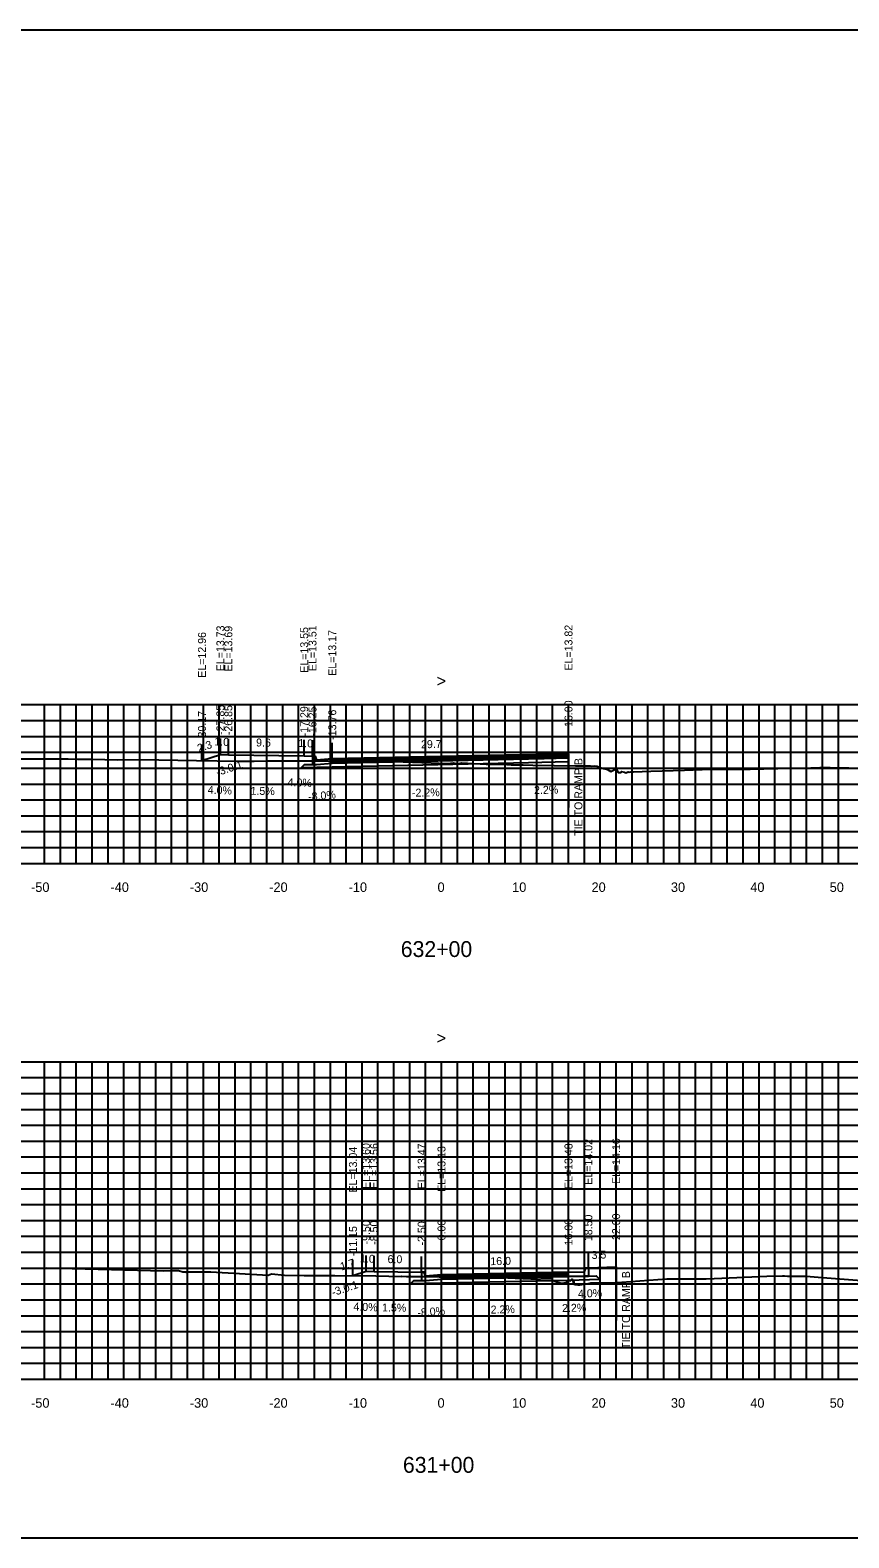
# Model space of a CAD drawing. Extents: x 1797645 to 1803805, y 248417 to 250269.
# Drawn here: x 1803599.2 to 1803702.3, y 250079.4 to 250269.4 of the extents above; entities that cross this region are included whole.
import ezdxf

# ---------------------------------------------------------------- set-up
doc = ezdxf.new("R2010")
doc.units = 0
for name, color, linetype in [('1', 7, 'Continuous'), ('10', 7, 'Continuous'), ('3', 7, 'Continuous'), ('4', 7, 'Continuous'), ('60', 7, 'Continuous'), ('BASE', 7, 'Continuous'), ('CL-CNST', 7, 'Continuous'), ('Level 62', 7, 'Continuous'), ('LOWER BINDER', 7, 'Continuous'), ('M-ROADS', 7, 'Continuous'), ('UPPER BINDER', 7, 'Continuous'), ('WEARING', 7, 'Continuous')]:
    doc.layers.add(name, color=color, linetype=linetype)

msp = doc.modelspace()

# ---------------------------------------------------------------- linework, layer by layer
for p, q in [((1803620.83, 250177.39), (1803620.83, 250179.39)), ((1803623.15, 250178.16), (1803623.15, 250180.16)), ((1803624.15, 250178.12), (1803624.15, 250180.12)), ((1803633.71, 250177.98), (1803633.71, 250179.98)), ((1803634.75, 250177.94), (1803634.75, 250179.94)), ((1803637.24, 250177.6), (1803637.24, 250179.6)), ((1803667, 250178.25), (1803667, 250180.25)), ((1803639.85, 250112.48), (1803639.85, 250114.48)), ((1803641.5, 250113.03), (1803641.5, 250115.03)), ((1803642.5, 250112.99), (1803642.5, 250114.99)), ((1803648.5, 250112.9), (1803648.5, 250114.9)), ((1803648.5, 250112.9), (1803648.5, 250114.9)), ((1803651, 250112.56), (1803651, 250114.56)), ((1803667, 250112.91), (1803667, 250114.91)), ((1803669.5, 250113.45), (1803669.5, 250115.45)), ((1803673, 250113.59), (1803673, 250115.59))]:
    msp.add_line(p, q)
for points in [[(1803501, 250079.43), (1803801, 250079.43), (1803801, 250269.43), (1803501, 250269.43)], [(1803637.24, 250177.6), (1803635.24, 250177.44), (1803635.08, 250177.94), (1803634.75, 250177.94), (1803634.74, 250176.91), (1803635.24, 250176.91), (1803637.24, 250177.07)], [(1803651, 250112.56), (1803649, 250112.4), (1803648.83, 250112.9), (1803648.5, 250112.9), (1803648.5, 250111.87), (1803649, 250111.87), (1803651, 250112.03)], [(1803667, 250112.91), (1803669, 250112.95), (1803669.17, 250113.45), (1803669.5, 250113.45), (1803669.5, 250112.42), (1803669, 250112.42), (1803667, 250112.38)]]:
    msp.add_lwpolyline(points, close=True)
at = {"layer": '3'}
for p, q in [((1803667, 250178.25), (1803667, 250171.47)), ((1803673, 250113.59), (1803673, 250106.81))]:
    msp.add_line(p, q, dxfattribs=at)
at = {"layer": '60'}
for p, q in [((1803501, 250164.43), (1803801, 250164.43)), ((1803601, 250164.37), (1803601, 250164.43)), ((1803611, 250164.37), (1803611, 250164.43)), ((1803621, 250164.37), (1803621, 250164.43)), ((1803631, 250164.37), (1803631, 250164.43)), ((1803641, 250164.37), (1803641, 250164.43)), ((1803651, 250164.37), (1803651, 250164.43)), ((1803661, 250164.37), (1803661, 250164.43)), ((1803671, 250164.37), (1803671, 250164.43)), ((1803681, 250164.37), (1803681, 250164.43)), ((1803691, 250164.37), (1803691, 250164.43)), ((1803701, 250164.37), (1803701, 250164.43)), ((1803501, 250099.43), (1803801, 250099.43)), ((1803601, 250099.37), (1803601, 250099.43)), ((1803611, 250099.37), (1803611, 250099.43)), ((1803621, 250099.37), (1803621, 250099.43)), ((1803631, 250099.37), (1803631, 250099.43)), ((1803641, 250099.37), (1803641, 250099.43)), ((1803651, 250099.37), (1803651, 250099.43)), ((1803661, 250099.37), (1803661, 250099.43)), ((1803671, 250099.37), (1803671, 250099.43)), ((1803681, 250099.37), (1803681, 250099.43)), ((1803691, 250099.37), (1803691, 250099.43)), ((1803701, 250099.37), (1803701, 250099.43))]:
    msp.add_line(p, q, dxfattribs=at)
at = {"layer": 'BASE'}
for points in [[(1803637.24, 250177.07), (1803661.94, 250177.61), (1803663.94, 250177.66), (1803667, 250177.72), (1803667, 250177.22), (1803661.94, 250177.11), (1803637.24, 250176.57), (1803633.34, 250176.48), (1803633.74, 250176.89), (1803634.74, 250176.91), (1803635.24, 250176.91)], [(1803651, 250112.03), (1803667, 250112.38), (1803669, 250112.42), (1803669.5, 250112.42), (1803670.5, 250112.45), (1803670.98, 250111.97), (1803667, 250111.88), (1803651, 250111.53), (1803647.09, 250111.44), (1803647.5, 250111.85), (1803648.5, 250111.87), (1803649, 250111.87)]]:
    msp.add_lwpolyline(points, close=True, dxfattribs=at)
at = {"layer": 'CL-CNST'}
for points in [[(1803620.83, 250177.39), (1803623.15, 250178.16), (1803624.15, 250178.12), (1803633.71, 250177.98), (1803634.75, 250177.94), (1803635.08, 250177.94), (1803635.24, 250177.44), (1803637.24, 250177.6), (1803661.94, 250178.14), (1803667, 250178.25)], [(1803639.85, 250112.48), (1803641.5, 250113.03), (1803642.5, 250112.99), (1803648.5, 250112.9), (1803648.5, 250112.9), (1803648.83, 250112.9), (1803649, 250112.4), (1803651, 250112.56), (1803667, 250112.91), (1803669, 250112.95), (1803669.17, 250113.45), (1803669.5, 250113.45), (1803673, 250113.59)]]:
    msp.add_lwpolyline(points, dxfattribs=at)
at = {"layer": 'Level 62'}
for p, q in [((1803501, 250184.43), (1803801, 250184.43)), ((1803601, 250164.43), (1803601, 250184.43)), ((1803603, 250164.43), (1803603, 250184.43)), ((1803605, 250164.43), (1803605, 250184.43)), ((1803607, 250164.43), (1803607, 250184.43)), ((1803609, 250164.43), (1803609, 250184.43)), ((1803611, 250164.43), (1803611, 250184.43)), ((1803613, 250164.43), (1803613, 250184.43)), ((1803615, 250164.43), (1803615, 250184.43)), ((1803617, 250164.43), (1803617, 250184.43)), ((1803619, 250164.43), (1803619, 250184.43)), ((1803621, 250164.43), (1803621, 250184.43)), ((1803623, 250164.43), (1803623, 250184.43)), ((1803625, 250164.43), (1803625, 250184.43)), ((1803627, 250164.43), (1803627, 250184.43)), ((1803629, 250164.43), (1803629, 250184.43)), ((1803631, 250164.43), (1803631, 250184.43)), ((1803633, 250164.43), (1803633, 250184.43)), ((1803635, 250164.43), (1803635, 250184.43)), ((1803637, 250164.43), (1803637, 250184.43)), ((1803639, 250164.43), (1803639, 250184.43)), ((1803641, 250164.43), (1803641, 250184.43)), ((1803643, 250164.43), (1803643, 250184.43)), ((1803645, 250164.43), (1803645, 250184.43)), ((1803647, 250164.43), (1803647, 250184.43)), ((1803649, 250164.43), (1803649, 250184.43)), ((1803651, 250164.43), (1803651, 250184.43)), ((1803653, 250164.43), (1803653, 250184.43)), ((1803655, 250164.43), (1803655, 250184.43)), ((1803657, 250164.43), (1803657, 250184.43)), ((1803659, 250164.43), (1803659, 250184.43)), ((1803661, 250164.43), (1803661, 250184.43)), ((1803663, 250164.43), (1803663, 250184.43)), ((1803665, 250164.43), (1803665, 250184.43)), ((1803667, 250164.43), (1803667, 250184.43)), ((1803669, 250164.43), (1803669, 250184.43)), ((1803671, 250164.43), (1803671, 250184.43)), ((1803673, 250164.43), (1803673, 250184.43)), ((1803675, 250164.43), (1803675, 250184.43)), ((1803677, 250164.43), (1803677, 250184.43)), ((1803679, 250164.43), (1803679, 250184.43)), ((1803681, 250164.43), (1803681, 250184.43)), ((1803683, 250164.43), (1803683, 250184.43)), ((1803685, 250164.43), (1803685, 250184.43)), ((1803687, 250164.43), (1803687, 250184.43)), ((1803689, 250164.43), (1803689, 250184.43)), ((1803691, 250164.43), (1803691, 250184.43)), ((1803693, 250164.43), (1803693, 250184.43)), ((1803695, 250164.43), (1803695, 250184.43)), ((1803697, 250164.43), (1803697, 250184.43)), ((1803699, 250164.43), (1803699, 250184.43)), ((1803701, 250164.43), (1803701, 250184.43)), ((1803501, 250182.43), (1803801, 250182.43)), ((1803501, 250180.43), (1803801, 250180.43)), ((1803501, 250178.43), (1803801, 250178.43)), ((1803501, 250176.43), (1803801, 250176.43)), ((1803501, 250174.43), (1803801, 250174.43)), ((1803501, 250172.43), (1803801, 250172.43)), ((1803501, 250170.43), (1803801, 250170.43)), ((1803501, 250168.43), (1803801, 250168.43)), ((1803501, 250166.43), (1803801, 250166.43)), ((1803501, 250164.43), (1803801, 250164.43)), ((1803501, 250139.43), (1803801, 250139.43)), ((1803601, 250099.43), (1803601, 250139.43)), ((1803603, 250099.43), (1803603, 250139.43)), ((1803605, 250099.43), (1803605, 250139.43)), ((1803607, 250099.43), (1803607, 250139.43)), ((1803609, 250099.43), (1803609, 250139.43)), ((1803611, 250099.43), (1803611, 250139.43)), ((1803613, 250099.43), (1803613, 250139.43)), ((1803615, 250099.43), (1803615, 250139.43)), ((1803617, 250099.43), (1803617, 250139.43)), ((1803619, 250099.43), (1803619, 250139.43)), ((1803621, 250099.43), (1803621, 250139.43)), ((1803623, 250099.43), (1803623, 250139.43)), ((1803625, 250099.43), (1803625, 250139.43)), ((1803627, 250099.43), (1803627, 250139.43)), ((1803629, 250099.43), (1803629, 250139.43)), ((1803631, 250099.43), (1803631, 250139.43)), ((1803633, 250099.43), (1803633, 250139.43)), ((1803635, 250099.43), (1803635, 250139.43)), ((1803637, 250099.43), (1803637, 250139.43)), ((1803639, 250099.43), (1803639, 250139.43)), ((1803641, 250099.43), (1803641, 250139.43)), ((1803643, 250099.43), (1803643, 250139.43)), ((1803645, 250099.43), (1803645, 250139.43)), ((1803647, 250099.43), (1803647, 250139.43)), ((1803649, 250099.43), (1803649, 250139.43)), ((1803651, 250099.43), (1803651, 250139.43)), ((1803653, 250099.43), (1803653, 250139.43)), ((1803655, 250099.43), (1803655, 250139.43)), ((1803657, 250099.43), (1803657, 250139.43)), ((1803659, 250099.43), (1803659, 250139.43)), ((1803661, 250099.43), (1803661, 250139.43)), ((1803663, 250099.43), (1803663, 250139.43)), ((1803665, 250099.43), (1803665, 250139.43)), ((1803667, 250099.43), (1803667, 250139.43)), ((1803669, 250099.43), (1803669, 250139.43)), ((1803671, 250099.43), (1803671, 250139.43)), ((1803673, 250099.43), (1803673, 250139.43)), ((1803675, 250099.43), (1803675, 250139.43)), ((1803677, 250099.43), (1803677, 250139.43)), ((1803679, 250099.43), (1803679, 250139.43)), ((1803681, 250099.43), (1803681, 250139.43)), ((1803683, 250099.43), (1803683, 250139.43)), ((1803685, 250099.43), (1803685, 250139.43)), ((1803687, 250099.43), (1803687, 250139.43)), ((1803689, 250099.43), (1803689, 250139.43)), ((1803691, 250099.43), (1803691, 250139.43)), ((1803693, 250099.43), (1803693, 250139.43)), ((1803695, 250099.43), (1803695, 250139.43)), ((1803697, 250099.43), (1803697, 250139.43)), ((1803699, 250099.43), (1803699, 250139.43)), ((1803701, 250099.43), (1803701, 250139.43)), ((1803501, 250137.43), (1803801, 250137.43)), ((1803501, 250135.43), (1803801, 250135.43)), ((1803501, 250133.43), (1803801, 250133.43)), ((1803501, 250131.43), (1803801, 250131.43)), ((1803501, 250129.43), (1803801, 250129.43)), ((1803501, 250127.43), (1803801, 250127.43)), ((1803501, 250125.43), (1803801, 250125.43)), ((1803501, 250123.43), (1803801, 250123.43)), ((1803501, 250121.43), (1803801, 250121.43)), ((1803501, 250119.43), (1803801, 250119.43)), ((1803501, 250117.43), (1803801, 250117.43)), ((1803501, 250115.43), (1803801, 250115.43)), ((1803501, 250113.43), (1803801, 250113.43)), ((1803501, 250111.43), (1803801, 250111.43)), ((1803501, 250109.43), (1803801, 250109.43)), ((1803501, 250107.43), (1803801, 250107.43)), ((1803501, 250105.43), (1803801, 250105.43)), ((1803501, 250103.43), (1803801, 250103.43)), ((1803501, 250101.43), (1803801, 250101.43)), ((1803501, 250099.43), (1803801, 250099.43))]:
    msp.add_line(p, q, dxfattribs=at)
at = {"layer": 'LOWER BINDER'}
for points in [[(1803667, 250177.72), (1803667, 250177.91), (1803637.24, 250177.26), (1803637.24, 250177.07)], [(1803667, 250112.38), (1803667, 250112.38), (1803667, 250112.57), (1803651, 250112.22), (1803651, 250112.03)]]:
    msp.add_lwpolyline(points, close=True, dxfattribs=at)
at = {"layer": 'M-ROADS'}
for points in [[(1803597.76, 250177.62), (1803599.6, 250177.61), (1803603.96, 250177.59), (1803605.15, 250177.58), (1803606.98, 250177.57), (1803610.2, 250177.49), (1803613.05, 250177.53), (1803620.12, 250177.4), (1803622.76, 250177.37), (1803625.38, 250177.33), (1803626.46, 250177.33), (1803627.39, 250177.33), (1803628.88, 250177.37), (1803634.65, 250177.36), (1803640.07, 250177.31), (1803641.61, 250177.33), (1803642.89, 250177.35), (1803646.18, 250177.24), (1803649.71, 250177.11), (1803651.75, 250177.02), (1803652.53, 250177.09), (1803653.05, 250176.99), (1803653.5, 250177.09), (1803656.62, 250176.92), (1803658.79, 250176.93), (1803659.25, 250176.9), (1803659.78, 250176.86), (1803660.67, 250176.85), (1803660.76, 250176.86), (1803661.28, 250176.85), (1803662.52, 250176.82), (1803667.9, 250176.73), (1803669.72, 250176.71), (1803669.91, 250176.68), (1803670.33, 250176.71), (1803670.59, 250176.68), (1803671.19, 250176.41), (1803671.9, 250176.26), (1803672.33, 250176.02), (1803672.84, 250176.26), (1803672.97, 250176.35), (1803672.99, 250176.38), (1803673.2, 250175.94), (1803673.26, 250175.89), (1803673.58, 250175.9), (1803673.59, 250175.9), (1803673.67, 250176), (1803674.05, 250175.91), (1803674.23, 250175.86), (1803674.5, 250175.97), (1803674.66, 250175.93), (1803674.86, 250175.97), (1803675.19, 250175.97), (1803677.35, 250176.03), (1803681.63, 250176.19), (1803684.94, 250176.31), (1803685.61, 250176.32), (1803687.27, 250176.32), (1803687.72, 250176.3), (1803687.76, 250176.3), (1803687.88, 250176.3), (1803689.9, 250176.3), (1803695.07, 250176.43), (1803697.54, 250176.48), (1803698.65, 250176.5), (1803699.9, 250176.5), (1803700.07, 250176.49), (1803702.33, 250176.49)], [(1803601.2, 250113.48), (1803615.97, 250113.08), (1803617.08, 250113.11), (1803617.87, 250113.12), (1803618.42, 250112.94), (1803618.83, 250112.94), (1803618.84, 250112.87), (1803619.05, 250112.94), (1803619.29, 250112.94), (1803621.95, 250112.96), (1803629.18, 250112.55), (1803629.59, 250112.69), (1803631.22, 250112.55), (1803633.7, 250112.5), (1803637.57, 250112.5), (1803642.73, 250112.44), (1803645.99, 250112.35), (1803646, 250112.38), (1803646.02, 250112.39), (1803646.58, 250112.35), (1803647.02, 250112.38), (1803647.09, 250112.39), (1803647.1, 250112.38), (1803647.81, 250112.38), (1803649.49, 250112.36), (1803650.69, 250112.34), (1803651.63, 250112.33), (1803651.99, 250112.33), (1803652.06, 250112.27), (1803652.28, 250112.32), (1803652.62, 250112.34), (1803652.65, 250112.34), (1803653.96, 250112.3), (1803656.52, 250112.31), (1803660.27, 250112.15), (1803663.21, 250112.03), (1803663.78, 250112.1), (1803664.82, 250112.1), (1803665.18, 250111.76), (1803666.11, 250111.53), (1803666.7, 250111.63), (1803667.13, 250111.87), (1803667.23, 250111.81), (1803667.23, 250111.85), (1803667.24, 250111.81), (1803667.25, 250111.87), (1803667.44, 250112.05), (1803667.55, 250111.81), (1803667.62, 250111.56), (1803667.63, 250111.69), (1803667.65, 250111.73), (1803667.71, 250111.4), (1803667.72, 250111.41), (1803667.72, 250111.41), (1803667.72, 250111.4), (1803667.73, 250111.4), (1803667.82, 250111.36), (1803667.88, 250111.35), (1803668.18, 250111.31), (1803668.44, 250111.32), (1803669.7, 250111.53), (1803669.82, 250111.55), (1803669.89, 250111.55), (1803670.25, 250111.56), (1803671.72, 250111.56), (1803672.59, 250111.56), (1803678.26, 250111.98), (1803679.4, 250112.06), (1803680.31, 250112.06), (1803681.82, 250112.06), (1803681.9, 250112.06), (1803683.15, 250112.06), (1803684.07, 250112.06), (1803684.36, 250112.06), (1803685.33, 250112.11), (1803691.98, 250112.41), (1803693.95, 250112.43), (1803694.2, 250112.43), (1803694.57, 250112.41), (1803696.49, 250112.41), (1803696.95, 250112.41), (1803698.45, 250112.3), (1803703.89, 250111.88)]]:
    msp.add_lwpolyline(points, dxfattribs=at)
at = {"layer": 'UPPER BINDER'}
for points in [[(1803667, 250177.91), (1803667, 250178.1), (1803637.24, 250177.45), (1803637.24, 250177.26)], [(1803667, 250112.57), (1803667, 250112.76), (1803651, 250112.41), (1803651, 250112.22)]]:
    msp.add_lwpolyline(points, close=True, dxfattribs=at)
at = {"layer": 'WEARING'}
for points in [[(1803667, 250178.1), (1803667, 250178.25), (1803637.24, 250177.6), (1803637.24, 250177.45)], [(1803667, 250112.76), (1803667, 250112.91), (1803651, 250112.56), (1803651, 250112.41)]]:
    msp.add_lwpolyline(points, close=True, dxfattribs=at)

# ---------------------------------------------------------------- texts
for p in [(1803622.78, 250175.41), (1803637.35, 250109.86)]:
    msp.add_text('-3.0:1', height=1, rotation=18.4349).set_placement(p)
at = {"layer": '1'}
for s, p in [('632+00', (1803645.87, 250152.63)), ('631+00', (1803646.14, 250087.63))]:
    msp.add_text(s, height=2, dxfattribs=at).set_placement(p)
at = {"layer": '10'}
for s, p in [('-50', (1803599.3, 250160.83)), ('-40', (1803609.3, 250160.83)), ('-30', (1803619.3, 250160.83)), ('-20', (1803629.3, 250160.83)), ('-10', (1803639.3, 250160.83)), ('0', (1803650.5, 250160.83)), ('10', (1803659.9, 250160.83)), ('20', (1803669.9, 250160.83)), ('30', (1803679.9, 250160.83)), ('40', (1803689.9, 250160.83)), ('50', (1803699.9, 250160.83)), ('-50', (1803599.3, 250095.83)), ('-40', (1803609.3, 250095.83)), ('-30', (1803619.3, 250095.83)), ('-20', (1803629.3, 250095.83)), ('-10', (1803639.3, 250095.83)), ('0', (1803650.5, 250095.83)), ('10', (1803659.9, 250095.83)), ('20', (1803669.9, 250095.83)), ('30', (1803679.9, 250095.83)), ('40', (1803689.9, 250095.83)), ('50', (1803699.9, 250095.83))]:
    msp.add_text(s, height=1.2, dxfattribs=at).set_placement(p)
at = {"layer": '3'}
for s, p in [('EL=13.73', (1803623.65, 250188.64)), ('EL=13.69', (1803624.65, 250188.6)), ('EL=13.55', (1803634.21, 250188.45)), ('EL=13.51', (1803635.25, 250188.66)), ('EL=13.82', (1803667.5, 250188.73)), ('EL=12.96', (1803621.33, 250187.82)), ('EL=13.17', (1803637.74, 250188.07)), ('16.00', (1803667.5, 250181.62)), ('-30.17', (1803621.33, 250179.85)), ('-27.85', (1803623.65, 250180.62)), ('-26.85', (1803624.65, 250180.58)), ('-17.29', (1803634.21, 250180.44)), ('-16.25', (1803635.25, 250180.4)), ('-13.76', (1803637.74, 250180.01)), ('TIE TO RAMP B', (1803668.75, 250167.9)), ('EL=14.02', (1803670, 250123.93)), ('EL=14.16', (1803673.5, 250124.02)), ('EL=13.04', (1803640.35, 250122.95)), ('EL=13.60', (1803642, 250123.42)), ('EL=13.56', (1803643, 250123.41)), ('EL=13.47', (1803649, 250123.37)), ('EL=13.47', (1803649, 250123.37)), ('EL=13.13', (1803651.5, 250123.03)), ('EL=13.48', (1803667.5, 250123.38)), ('18.50', (1803670, 250116.82)), ('22.00', (1803673.5, 250116.96)), ('-11.15', (1803640.35, 250114.93)), ('-9.50', (1803642, 250116.4)), ('-8.50', (1803643, 250116.36)), ('-2.50', (1803649, 250116.27)), ('-2.50', (1803649, 250116.27)), ('0.00', (1803651.5, 250116.92)), ('16.00', (1803667.5, 250116.28)), ('TIE TO RAMP B', (1803674.74, 250103.24))]:
    msp.add_text(s, height=1, rotation=90, dxfattribs=at).set_placement(p)
at = {"layer": '4'}
for s, rotation, p in [('2.3', 18.4349, (1803620.43, 250178.42)), ('1.0', 357.7094, (1803622.37, 250179.3)), ('9.6', 359.1406, (1803627.64, 250179.17)), ('1.0', 357.7094, (1803632.95, 250179.11)), ('29.7', 1.2603, (1803648.43, 250178.93)), ('4.0%', 357.7094, (1803631.6, 250174.18)), ('4.0%', 357.7094, (1803621.54, 250173.22)), ('1.5%', 359.1406, (1803626.94, 250173.08)), ('-8.0%', 4.5739, (1803634.24, 250172.34)), ('-2.2%', 1.2603, (1803647.29, 250172.82)), ('2.2%', 1.2603, (1803662.67, 250173.16)), ('1.7', 18.4349, (1803638.43, 250113.11)), ('1.0', 357.7094, (1803640.72, 250114.16)), ('6.0', 359.1406, (1803644.2, 250114.06)), ('16.0', 1.2603, (1803657.16, 250113.79)), ('3.5', 2.2906, (1803669.92, 250114.57)), ('4.0%', 2.2906, (1803668.21, 250109.69)), ('4.0%', 357.7094, (1803639.89, 250108.09)), ('1.5%', 359.1406, (1803643.51, 250107.97)), ('-8.0%', 4.5739, (1803648, 250107.3)), ('2.2%', 1.2603, (1803657.2, 250107.69)), ('2.2%', 1.2603, (1803666.2, 250107.89))]:
    msp.add_text(s, height=1, rotation=rotation, dxfattribs=at).set_placement(p)
at = {"layer": '60'}
for p in [(1803650.39, 250186.68), (1803650.39, 250141.68)]:
    msp.add_text('>', height=1.5, dxfattribs=at).set_placement(p)

doc.saveas('drawing.dxf')
